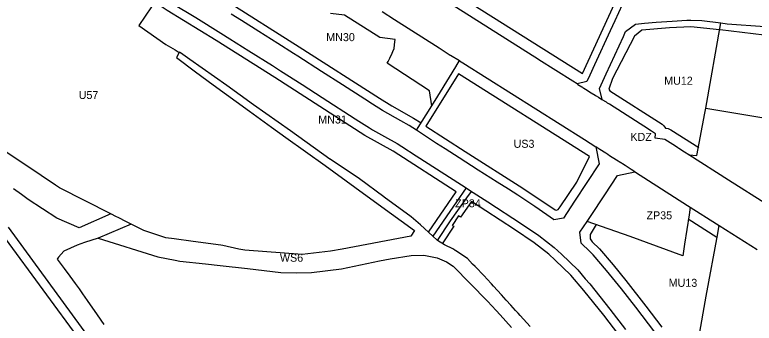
# Model space of a CAD drawing. Extents: x 7428080 to 7432143, y 5545880 to 5549217.
# Drawn here: x 7430217 to 7430730, y 5547228 to 5547442 of the extents above; entities that cross this region are included whole.
import ezdxf

# ---------------------------------------------------------------- set-up
doc = ezdxf.new("R2010")
doc.units = 0
for name, color, linetype in [('CZ_L_linie rozgraniczające tereny o różnym przeznaczeniu oraz różnych warunkach ich zabudowy i zagospodarowania', 7, 'Continuous'), ('CZ_L_maksymalne nieprzekraczalne linie zabudowy', 7, 'Continuous'), ('CZ_L_opisy_linie rozgraniczające tereny o różnym przeznaczeniu oraz różnych warunkach ich zabudowy i zagospodarowania', 7, 'Continuous')]:
    doc.layers.add(name, color=color, linetype=linetype)

msp = doc.modelspace()

# ---------------------------------------------------------------- linework, layer by layer
at = {"layer": 'CZ_L_linie rozgraniczające tereny o różnym przeznaczeniu oraz różnych warunkach ich zabudowy i zagospodarowania'}
for p, q in [((7430580.2, 5547411.38), (7430505.96, 5547458.41)), ((7430317.15, 5547455.65), (7430303.32, 5547434.87)), ((7430326.12, 5547450.43), (7430342.6, 5547440.45)), ((7430638.01, 5547449.24), (7430632.96, 5547438.23)), ((7430374.31, 5547438.38), (7430367.18, 5547442.88)), ((7430445.67, 5547442.14), (7430436.1, 5547443.27)), ((7430471.7, 5547444.61), (7430480.33, 5547439.14)), ((7430342.6, 5547440.45), (7430360.06, 5547429.64)), ((7430386.37, 5547430.77), (7430374.31, 5547438.38)), ((7430470.08, 5547426.57), (7430445.67, 5547442.14)), ((7430480.33, 5547439.14), (7430511.37, 5547419.47)), ((7430632.96, 5547438.23), (7430629.75, 5547431.23)), ((7430661.56, 5547437.18), (7430672.7, 5547437.93)), ((7430672.7, 5547437.93), (7430682.86, 5547438.55)), ((7430682.86, 5547438.55), (7430685.75, 5547438.73)), ((7430685.75, 5547438.73), (7430693.18, 5547438.3)), ((7430693.18, 5547438.3), (7430706.5, 5547436.7)), ((7430303.32, 5547434.87), (7430321.96, 5547421.75)), ((7430640.5, 5547430.68), (7430647.32, 5547435.98)), ((7430647.32, 5547435.98), (7430653.46, 5547436.58)), ((7430653.46, 5547436.58), (7430661.56, 5547437.18)), ((7430695.95, 5547377.64), (7430706.5, 5547436.7)), ((7430706.5, 5547436.7), (7430710.81, 5547436.18)), ((7430710.81, 5547436.18), (7430736.98, 5547434.26)), ((7430360.06, 5547429.64), (7430366.16, 5547425.79)), ((7430399.61, 5547422.42), (7430386.37, 5547430.77)), ((7430629.75, 5547431.23), (7430618.98, 5547407.74)), ((7430627.05, 5547401.35), (7430638.96, 5547427.32)), ((7430638.96, 5547427.32), (7430640.5, 5547430.68)), ((7430366.16, 5547425.79), (7430379.49, 5547417.38)), ((7430410.47, 5547415.57), (7430399.61, 5547422.42)), ((7430480.78, 5547425.21), (7430470.08, 5547426.57)), ((7430480.38, 5547421.43), (7430480.62, 5547423.67)), ((7430480.62, 5547423.67), (7430480.63, 5547423.7)), ((7430480.63, 5547423.7), (7430480.78, 5547425.15)), ((7430480.78, 5547425.15), (7430480.78, 5547425.21)), ((7430321.96, 5547421.75), (7430328.27, 5547418.06)), ((7430328.27, 5547418.06), (7430331.23, 5547416.33)), ((7430379.49, 5547417.38), (7430395.75, 5547407.12)), ((7430479.16, 5547416.87), (7430480.12, 5547418.92)), ((7430480.12, 5547418.92), (7430480.38, 5547421.43)), ((7430511.37, 5547419.47), (7430518.86, 5547414.46)), ((7430331.26, 5547416.3), (7430329.25, 5547412.77)), ((7430329.25, 5547412.77), (7430342.47, 5547402.91)), ((7430331.23, 5547416.33), (7430331.26, 5547416.3)), ((7430331.31, 5547416.37), (7430331.26, 5547416.3)), ((7430331.99, 5547415.93), (7430331.31, 5547416.37)), ((7430338.44, 5547411.4), (7430331.99, 5547415.93)), ((7430413.36, 5547413.73), (7430410.47, 5547415.57)), ((7430429.78, 5547403.14), (7430413.36, 5547413.73)), ((7430475.89, 5547409.9), (7430477.03, 5547412.34)), ((7430477.03, 5547412.34), (7430478.64, 5547415.77)), ((7430478.64, 5547415.77), (7430479.16, 5547416.87)), ((7430518.86, 5547414.46), (7430518.95, 5547414.41)), ((7430518.95, 5547414.41), (7430519.06, 5547414.33)), ((7430519.06, 5547414.33), (7430525.34, 5547410.56)), ((7430364.13, 5547393.32), (7430338.44, 5547411.4)), ((7430395.75, 5547407.12), (7430401.44, 5547403.53)), ((7430475.36, 5547408.77), (7430475.89, 5547409.9)), ((7430504.67, 5547389.68), (7430475.36, 5547408.77)), ((7430522.74, 5547406.28), (7430525.34, 5547410.56)), ((7430525.34, 5547410.56), (7430525.36, 5547410.54)), ((7430525.36, 5547410.54), (7430525.49, 5547410.46)), ((7430525.49, 5547410.46), (7430527.73, 5547409.11)), ((7430527.73, 5547409.11), (7430611.9, 5547355.79)), ((7430580.32, 5547411.3), (7430580.2, 5547411.38)), ((7430580.42, 5547411.24), (7430580.32, 5547411.3)), ((7430603.96, 5547396.33), (7430580.42, 5547411.24)), ((7430618.98, 5547407.74), (7430615.68, 5547400.53)), ((7430342.47, 5547402.91), (7430354.78, 5547393.73)), ((7430401.44, 5547403.53), (7430416.34, 5547393.96)), ((7430444.4, 5547393.7), (7430429.78, 5547403.14)), ((7430512.23, 5547389.01), (7430522.74, 5547406.28)), ((7430615.68, 5547400.53), (7430613.52, 5547395.99)), ((7430622.39, 5547391.2), (7430627.05, 5547401.35)), ((7430354.78, 5547393.73), (7430379.93, 5547375.53)), ((7430382.64, 5547379.89), (7430364.13, 5547393.32)), ((7430416.34, 5547393.96), (7430430.24, 5547384.99)), ((7430459.75, 5547383.79), (7430444.4, 5547393.7)), ((7430606.87, 5547394.48), (7430603.96, 5547396.33)), ((7430613.52, 5547395.99), (7430606.87, 5547394.48)), ((7430606.87, 5547394.48), (7430607.43, 5547394.13)), ((7430607.43, 5547394.13), (7430610.1, 5547392.44)), ((7430610.1, 5547392.44), (7430610.63, 5547392.1)), ((7430610.63, 5547392.1), (7430610.88, 5547391.94)), ((7430610.88, 5547391.94), (7430611.43, 5547391.59)), ((7430611.43, 5547391.59), (7430612.61, 5547390.85)), ((7430506.16, 5547379.23), (7430504.67, 5547389.68)), ((7430510.38, 5547385.96), (7430512.23, 5547389.01)), ((7430612.61, 5547390.85), (7430614.59, 5547389.59)), ((7430614.59, 5547389.59), (7430614.73, 5547389.49)), ((7430614.73, 5547389.49), (7430616.71, 5547388.24)), ((7430616.71, 5547388.24), (7430619.34, 5547386.58)), ((7430619.34, 5547386.58), (7430620.06, 5547386.13)), ((7430624.22, 5547383.5), (7430622.39, 5547391.2)), ((7430430.24, 5547384.99), (7430453.09, 5547370.24)), ((7430465.18, 5547380.29), (7430459.75, 5547383.79)), ((7430506.16, 5547379.23), (7430510.38, 5547385.96)), ((7430620.06, 5547386.13), (7430621.6, 5547385.16)), ((7430621.6, 5547385.16), (7430621.63, 5547385.14)), ((7430621.63, 5547385.14), (7430623.31, 5547384.07)), ((7430623.31, 5547384.07), (7430623.88, 5547383.71)), ((7430623.88, 5547383.71), (7430624.22, 5547383.5)), ((7430624.3, 5547383.44), (7430624.22, 5547383.5)), ((7430627.14, 5547381.65), (7430624.3, 5547383.44)), ((7430627.98, 5547381.12), (7430627.14, 5547381.65)), ((7430628, 5547381.1), (7430627.98, 5547381.12)), ((7430628.01, 5547381.09), (7430628, 5547381.1)), ((7430629.2, 5547380.34), (7430628.01, 5547381.09)), ((7430382.75, 5547379.81), (7430382.64, 5547379.89)), ((7430408.31, 5547361.97), (7430382.75, 5547379.81)), ((7430472.05, 5547375.89), (7430465.18, 5547380.29)), ((7430495.55, 5547362.28), (7430506.16, 5547379.23)), ((7430629.29, 5547380.28), (7430629.2, 5547380.34)), ((7430656.38, 5547363), (7430629.29, 5547380.28)), ((7430695.33, 5547374.23), (7430695.95, 5547377.64)), ((7430695.95, 5547377.64), (7430754.58, 5547367.81)), ((7430379.93, 5547375.53), (7430395.12, 5547364.5)), ((7430484.74, 5547368.81), (7430472.05, 5547375.89)), ((7430689.92, 5547344.66), (7430695.33, 5547374.23)), ((7430453.09, 5547370.24), (7430455.7, 5547368.55)), ((7430455.7, 5547368.55), (7430462.95, 5547363.88)), ((7430490.49, 5547365.59), (7430484.74, 5547368.81)), ((7430395.12, 5547364.5), (7430405.05, 5547357.29)), ((7430435.64, 5547342.27), (7430408.31, 5547361.97)), ((7430462.95, 5547363.88), (7430465.05, 5547362.62)), ((7430465.05, 5547362.62), (7430473.37, 5547357.98)), ((7430495.55, 5547362.28), (7430490.49, 5547365.59)), ((7430509.41, 5547353.19), (7430495.55, 5547362.28)), ((7430656.58, 5547362.87), (7430656.38, 5547363)), ((7430658.41, 5547361.7), (7430656.58, 5547362.87)), ((7430661.24, 5547359.89), (7430658.41, 5547361.7)), ((7430405.05, 5547357.29), (7430432.31, 5547337.76)), ((7430473.37, 5547357.98), (7430482.21, 5547353.04)), ((7430611.9, 5547355.79), (7430619.81, 5547350.74)), ((7430660.85, 5547356.8), (7430661.24, 5547359.89)), ((7430667.65, 5547355.81), (7430660.85, 5547356.8)), ((7430674.96, 5547351.15), (7430667.65, 5547355.81)), ((7430482.21, 5547353.04), (7430485.49, 5547350.94)), ((7430485.49, 5547350.94), (7430495.44, 5547344.42)), ((7430515.34, 5547349.38), (7430509.41, 5547353.19)), ((7430622.57, 5547348.98), (7430619.81, 5547350.74)), ((7430619.81, 5547350.74), (7430622.24, 5547338.97)), ((7430676.7, 5547350.03), (7430674.96, 5547351.15)), ((7430225.58, 5547337.5), (7430209.31, 5547348.41)), ((7430525.11, 5547343.07), (7430515.34, 5547349.38)), ((7430626.68, 5547346.36), (7430622.57, 5547348.98)), ((7430628.25, 5547345.36), (7430626.68, 5547346.36)), ((7430629.41, 5547344.62), (7430628.25, 5547345.36)), ((7430677.37, 5547349.61), (7430676.7, 5547350.03)), ((7430681.39, 5547347.04), (7430677.37, 5547349.61)), ((7430684.19, 5547345.26), (7430681.39, 5547347.04)), ((7430711.71, 5547327.7), (7430684.19, 5547345.26)), ((7430684.19, 5547345.26), (7430689.92, 5547344.66)), ((7430435.67, 5547342.25), (7430435.64, 5547342.27)), ((7430456.02, 5547328.69), (7430435.67, 5547342.25)), ((7430495.44, 5547344.42), (7430515.11, 5547331.75)), ((7430538.36, 5547334.69), (7430525.11, 5547343.07)), ((7430634.13, 5547341.61), (7430629.41, 5547344.62)), ((7430637.18, 5547339.66), (7430634.13, 5547341.61)), ((7430245.57, 5547324.1), (7430225.58, 5547337.5)), ((7430432.31, 5547337.76), (7430452.87, 5547322.81)), ((7430622.24, 5547338.97), (7430605.15, 5547313.1)), ((7430637.59, 5547339.4), (7430637.18, 5547339.66)), ((7430638.37, 5547338.9), (7430637.59, 5547339.4)), ((7430640.12, 5547337.78), (7430638.37, 5547338.9)), ((7430644.42, 5547335.05), (7430640.12, 5547337.78)), ((7430646.78, 5547333.54), (7430644.42, 5547335.05)), ((7430515.11, 5547331.75), (7430529.9, 5547322.35)), ((7430551.5, 5547326.37), (7430538.36, 5547334.69)), ((7430626.04, 5547317.52), (7430634.93, 5547330.97)), ((7430634.93, 5547330.97), (7430646.78, 5547333.54)), ((7430646.78, 5547333.54), (7430647.35, 5547333.17)), ((7430647.35, 5547333.17), (7430683.4, 5547310.18)), ((7430472.94, 5547316.18), (7430456.02, 5547328.69)), ((7430559.44, 5547321.35), (7430551.5, 5547326.37)), ((7430738.77, 5547310.44), (7430711.71, 5547327.7)), ((7430221.93, 5547317.66), (7430216.48, 5547321.68)), ((7430248.23, 5547322.31), (7430245.57, 5547324.1)), ((7430283.89, 5547304.22), (7430248.23, 5547322.31)), ((7430452.87, 5547322.81), (7430469.1, 5547311.1)), ((7430529.9, 5547322.35), (7430523.28, 5547312.7)), ((7430529.9, 5547322.35), (7430533.76, 5547319.9)), ((7430530.54, 5547315.51), (7430533.76, 5547319.9)), ((7430533.76, 5547319.9), (7430534.96, 5547319.13)), ((7430565.75, 5547317.35), (7430559.44, 5547321.35)), ((7430226.59, 5547314.23), (7430221.93, 5547317.66)), ((7430473.25, 5547315.95), (7430472.94, 5547316.18)), ((7430491.92, 5547302.3), (7430473.25, 5547315.95)), ((7430519.23, 5547299.35), (7430530.54, 5547315.51)), ((7430534.96, 5547319.13), (7430545.05, 5547312.7)), ((7430577.48, 5547309.33), (7430565.75, 5547317.35)), ((7430616.07, 5547302.43), (7430626.04, 5547317.52)), ((7430246.4, 5547301.38), (7430226.59, 5547314.23)), ((7430469.1, 5547311.1), (7430494.27, 5547292.65)), ((7430523.28, 5547312.7), (7430506.8, 5547288.76)), ((7430545.05, 5547312.7), (7430568.43, 5547297.34)), ((7430605.15, 5547313.1), (7430597.4, 5547301.33)), ((7430683.4, 5547310.18), (7430685.26, 5547308.99)), ((7430585.99, 5547303.61), (7430577.48, 5547309.33)), ((7430685.26, 5547308.99), (7430684.43, 5547303.59)), ((7430685.26, 5547308.99), (7430703.44, 5547297.4)), ((7430261.86, 5547294.5), (7430246.4, 5547301.38)), ((7430283.89, 5547304.22), (7430261.86, 5547294.5)), ((7430287.71, 5547302.28), (7430283.89, 5547304.22)), ((7430288.81, 5547301.72), (7430287.71, 5547302.28)), ((7430294.76, 5547298.7), (7430288.81, 5547301.72)), ((7430498.39, 5547296.57), (7430491.92, 5547302.3)), ((7430510.07, 5547285.74), (7430519.23, 5547299.35)), ((7430590.52, 5547300.33), (7430585.99, 5547303.61)), ((7430590.65, 5547300.23), (7430590.52, 5547300.33)), ((7430597.4, 5547301.33), (7430590.65, 5547300.23)), ((7430613.86, 5547299.08), (7430616.07, 5547302.43)), ((7430684.43, 5547303.59), (7430681.31, 5547283.37)), ((7430212.67, 5547295.01), (7430267.72, 5547219.77)), ((7430297.98, 5547297.07), (7430274.99, 5547287.45)), ((7430297.98, 5547297.07), (7430294.76, 5547298.7)), ((7430306.7, 5547292.64), (7430297.98, 5547297.07)), ((7430506.8, 5547288.76), (7430498.39, 5547296.57)), ((7430568.43, 5547297.34), (7430580.4, 5547289.17)), ((7430608.85, 5547291.49), (7430613.86, 5547299.08)), ((7430643.58, 5547288.62), (7430613.86, 5547299.08)), ((7430703.44, 5547297.4), (7430705.22, 5547296.26)), ((7430704.31, 5547290.91), (7430705.22, 5547296.26)), ((7430705.22, 5547296.26), (7430731.53, 5547279.48)), ((7430321.82, 5547287.72), (7430306.7, 5547292.64)), ((7430494.27, 5547292.65), (7430491.77, 5547288.75)), ((7430580.4, 5547289.17), (7430591.07, 5547280.93)), ((7430609.75, 5547283.89), (7430608.85, 5547291.49)), ((7430696.26, 5547247.28), (7430704.27, 5547290.69)), ((7430704.27, 5547290.69), (7430704.31, 5547290.91)), ((7430265.63, 5547284.35), (7430260.58, 5547282.67)), ((7430274.99, 5547287.45), (7430265.63, 5547284.35)), ((7430274.99, 5547287.45), (7430316.47, 5547274.55)), ((7430327.77, 5547286.87), (7430321.82, 5547287.72)), ((7430340.94, 5547285), (7430327.77, 5547286.87)), ((7430360.14, 5547282.49), (7430340.94, 5547285)), ((7430491.77, 5547288.75), (7430444, 5547279.71)), ((7430509.81, 5547285.98), (7430506.8, 5547288.76)), ((7430510.07, 5547285.74), (7430509.81, 5547285.98)), ((7430515.02, 5547282.71), (7430510.07, 5547285.74)), ((7430615.6, 5547278.28), (7430609.75, 5547283.89)), ((7430680.01, 5547275.06), (7430643.58, 5547288.62)), ((7430260.58, 5547282.67), (7430251.31, 5547278.51)), ((7430361.33, 5547282.33), (7430360.14, 5547282.49)), ((7430372.46, 5547279.72), (7430361.33, 5547282.33)), ((7430376.62, 5547279.09), (7430372.46, 5547279.72)), ((7430416.35, 5547276.12), (7430376.62, 5547279.09)), ((7430444, 5547279.71), (7430436.1, 5547278.41)), ((7430521.23, 5547279.73), (7430515.02, 5547282.71)), ((7430522.43, 5547278.93), (7430521.23, 5547279.73)), ((7430522.62, 5547278.8), (7430522.43, 5547278.93)), ((7430522.78, 5547278.68), (7430522.62, 5547278.8)), ((7430530.86, 5547273.24), (7430522.78, 5547278.68)), ((7430591.07, 5547280.93), (7430595.96, 5547276.34)), ((7430681.31, 5547283.37), (7430680.01, 5547275.06)), ((7430247.65, 5547274.22), (7430247.01, 5547273.47)), ((7430251.31, 5547278.51), (7430247.65, 5547274.22)), ((7430316.47, 5547274.55), (7430328.37, 5547272.11)), ((7430436.1, 5547278.41), (7430416.35, 5547276.12)), ((7430477.27, 5547273.09), (7430491.85, 5547275.48)), ((7430491.85, 5547275.48), (7430500.77, 5547275.64)), ((7430500.77, 5547275.64), (7430509.83, 5547273.69)), ((7430509.83, 5547273.69), (7430516.39, 5547270.94)), ((7430595.96, 5547276.34), (7430607.3, 5547265.41)), ((7430618, 5547275.95), (7430615.6, 5547278.28)), ((7430627.27, 5547265.09), (7430618, 5547275.95)), ((7430247.01, 5547273.47), (7430246.58, 5547272.96)), ((7430246.58, 5547272.96), (7430251.44, 5547266.37)), ((7430328.37, 5547272.11), (7430331.73, 5547271.41)), ((7430331.73, 5547271.41), (7430349.43, 5547269.69)), ((7430349.43, 5547269.69), (7430359.66, 5547268.54)), ((7430359.66, 5547268.54), (7430378.43, 5547266.38)), ((7430443.69, 5547266.15), (7430469.98, 5547271.78)), ((7430469.98, 5547271.78), (7430477.27, 5547273.09)), ((7430516.39, 5547270.94), (7430521.08, 5547267.96)), ((7430534.49, 5547269.49), (7430530.86, 5547273.24)), ((7430536.17, 5547267.75), (7430534.49, 5547269.49)), ((7430251.44, 5547266.37), (7430255.32, 5547261.1)), ((7430378.43, 5547266.38), (7430401.55, 5547263.62)), ((7430401.55, 5547263.62), (7430412.28, 5547263.28)), ((7430412.28, 5547263.28), (7430422.94, 5547263.57)), ((7430422.94, 5547263.57), (7430443.69, 5547266.15)), ((7430521.08, 5547267.96), (7430544.69, 5547243.68)), ((7430542.36, 5547261.33), (7430536.17, 5547267.75)), ((7430607.3, 5547265.41), (7430612.48, 5547259.32)), ((7430635.64, 5547254.73), (7430627.27, 5547265.09)), ((7430255.32, 5547261.1), (7430259.06, 5547256.04)), ((7430544.58, 5547258.9), (7430542.36, 5547261.33)), ((7430547.45, 5547255.75), (7430544.58, 5547258.9)), ((7430612.48, 5547259.32), (7430615.58, 5547255.69)), ((7430259.06, 5547256.04), (7430261.88, 5547252.22)), ((7430548.88, 5547254.18), (7430547.45, 5547255.75)), ((7430554.47, 5547248.1), (7430548.88, 5547254.18)), ((7430615.58, 5547255.69), (7430629.65, 5547238.08)), ((7430637.64, 5547252.19), (7430635.64, 5547254.73)), ((7430261.88, 5547252.22), (7430264.23, 5547248.83)), ((7430264.23, 5547248.83), (7430267.42, 5547244.23)), ((7430557.76, 5547244.51), (7430554.47, 5547248.1)), ((7430647.47, 5547239.67), (7430637.64, 5547252.19)), ((7430267.42, 5547244.23), (7430274.38, 5547234.22)), ((7430544.69, 5547243.68), (7430550.81, 5547237.13)), ((7430557.79, 5547244.48), (7430557.76, 5547244.51)), ((7430561.03, 5547240.95), (7430557.79, 5547244.48)), ((7430691.24, 5547218.28), (7430696.26, 5547247.28)), ((7430564.28, 5547237.32), (7430561.03, 5547240.95)), ((7430629.65, 5547238.08), (7430640.5, 5547224.17)), ((7430660.77, 5547222.18), (7430647.47, 5547239.67)), ((7430274.38, 5547234.22), (7430279.05, 5547227.49)), ((7430550.81, 5547237.13), (7430553.53, 5547234.13)), ((7430553.53, 5547234.13), (7430561.35, 5547225.52)), ((7430566.07, 5547235.33), (7430564.28, 5547237.32)), ((7430567.38, 5547233.87), (7430566.07, 5547235.33)), ((7430567.4, 5547233.85), (7430567.38, 5547233.87)), ((7430574.28, 5547226.17), (7430567.4, 5547233.85))]:
    msp.add_line(p, q, dxfattribs=at)
at = {"layer": 'CZ_L_maksymalne nieprzekraczalne linie zabudowy'}
for points in [[(7430516.8, 5547572.83), (7430507.68, 5547535.14), (7430507.14, 5547534.25), (7430506.38, 5547533.53), (7430505.47, 5547533.04), (7430504.45, 5547532.79), (7430503.15, 5547532.86), (7430498.44, 5547534.17), (7430497.99, 5547531.78), (7430498.12, 5547526.71), (7430499.25, 5547514.97), (7430506.06, 5547467.82), (7430610.64, 5547401.69), (7430632.86, 5547449.99), (7430632.01, 5547455.96), (7430610.29, 5547487.34), (7430561.88, 5547556.31), (7430557.25, 5547561.99), (7430555.54, 5547562.79), (7430516.81, 5547572.86)], [(7430503.8, 5547291.55), (7430523.13, 5547319.55), (7430479.33, 5547347.76), (7430459.83, 5547358.75), (7430397.54, 5547398.89), (7430356.88, 5547424.55), (7430322.82, 5547445.42), (7430315.28, 5547450.43), (7430303.09, 5547458.89), (7430279.12, 5547476.32), (7430270.95, 5547481.61), (7430264.96, 5547484.82), (7430254.27, 5547489.3), (7430235.92, 5547496.41), (7430221.07, 5547501.63), (7430203.91, 5547506.8), (7430175.96, 5547514.41), (7430170.84, 5547512.07), (7430160.94, 5547493.84), (7430140.6, 5547459.18), (7430136.14, 5547453.22), (7430119.58, 5547433.04), (7430119.2, 5547422.84)], [(7430362.34, 5547487.37), (7430360.29, 5547485.03), (7430359.24, 5547482.24), (7430351.63, 5547471.03), (7430349.51, 5547466.8), (7430347.01, 5547462.43), (7430363.19, 5547452.48), (7430414.4, 5547420.18), (7430469.87, 5547384.43), (7430478.55, 5547379.17), (7430493.59, 5547370.72), (7430498.77, 5547367.34)], [(7430705.6, 5547431.96), (7430685.65, 5547433.94), (7430670.87, 5547433.34), (7430651.74, 5547431.66), (7430646.68, 5547427.54), (7430631.33, 5547398.07), (7430628.8, 5547390.79), (7430629.54, 5547389.59), (7430665.84, 5547366.44), (7430667.05, 5547365.39), (7430668.21, 5547363.82), (7430669.99, 5547363.45), (7430671.82, 5547362.63), (7430691.28, 5547350.22)], [(7430748.68, 5547368.9), (7430754.58, 5547400.78), (7430758.84, 5547426.64), (7430736.55, 5547428.28), (7430705.89, 5547431.93)], [(7430524.65, 5547401.53), (7430502.06, 5547365.18), (7430529.25, 5547347.58), (7430569.26, 5547322.21), (7430591.78, 5547307.01), (7430592.65, 5547306.8), (7430593.66, 5547307.35), (7430595.17, 5547309.1), (7430606.61, 5547326.22), (7430615.35, 5547344.1), (7430524.65, 5547401.53)], [(7430635.89, 5547220.31), (7430625.29, 5547233.91), (7430611.64, 5547251.01), (7430602.56, 5547261.64), (7430591.75, 5547272.06), (7430587.17, 5547276.36), (7430577.04, 5547284.18), (7430563.57, 5547293.36), (7430533.61, 5547312.92), (7430525.98, 5547302.03), (7430524.71, 5547302.84), (7430520.39, 5547296.29), (7430521.55, 5547295.63), (7430513.39, 5547283.51)], [(7430703.68, 5547287.9), (7430683.89, 5547300.57)], [(7430619.99, 5547296.92), (7430615.88, 5547290.03), (7430615.99, 5547287.03), (7430617.41, 5547284.97), (7430622.46, 5547279.96), (7430631.83, 5547268.99), (7430640.68, 5547258.02), (7430654.54, 5547240.29), (7430665.61, 5547225.73)], [(7430197.83, 5547153.55), (7430221.84, 5547144.49), (7430226.69, 5547143.01), (7430227.3, 5547142.95), (7430239.41, 5547144.58), (7430242.53, 5547146.63), (7430278.61, 5547172.29), (7430279.73, 5547192.13), (7430263, 5547216.05), (7430210.93, 5547287.22)]]:
    msp.add_lwpolyline(points, dxfattribs=at)

# ---------------------------------------------------------------- texts
at = {"layer": 'CZ_L_opisy_linie rozgraniczające tereny o różnym przeznaczeniu oraz różnych warunkach ich zabudowy i zagospodarowania'}
for s, p in [('MN30', (7430433.07, 5547424.09)), ('MU12', (7430667.19, 5547393.87)), ('U57', (7430261.56, 5547383.98)), ('MN31', (7430427.52, 5547366.96)), ('US3', (7430562.87, 5547350.12)), ('KDZ', (7430643.78, 5547354.93)), ('ZP34', (7430522.37, 5547308.82)), ('ZP35', (7430654.95, 5547300.51)), ('WS6', (7430400.97, 5547271.07)), ('MU13', (7430670.32, 5547253.67))]:
    msp.add_text(s, height=5.549, dxfattribs=at).set_placement(p)

doc.saveas('drawing.dxf')
